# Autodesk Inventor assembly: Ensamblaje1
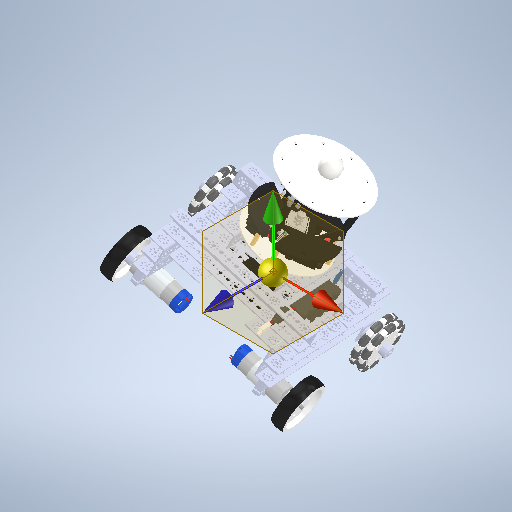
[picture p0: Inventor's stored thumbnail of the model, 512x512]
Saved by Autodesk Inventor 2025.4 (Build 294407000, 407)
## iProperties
Created: 2026-09
Part Number: Ensamblaje1
Document SubType Name: Assembly
Designer: usuario
Mass: 1778.88 g
Surface Area: 10785.4 cm^2
Volume: 1778.88 cm^3
Density: 1 g/cm^3
Author: usuario
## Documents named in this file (21)
- D:\Utec\Ciclo10\DSM\tetrix-solidworks-parts-1.snapshot.6\Nueva carpeta\DIseño\DIseño\Ensamblaje1.iam
- D:\Utec\Ciclo10\DSM\tetrix-solidworks-parts-1.snapshot.6\DIseño\Piezas\Tetrix 4 inch Dual Omni Wheel(2).ipt
- D:\Utec\Ciclo10\DSM\tetrix-solidworks-parts-1.snapshot.6\DIseño\Piezas\Tetrix 4 inch Wheel.ipt
- D:\Utec\Ciclo10\DSM\tetrix-solidworks-parts-1.snapshot.6\DIseño\Piezas\Tetrix 32mm Channel.ipt
- D:\Utec\Ciclo10\DSM\tetrix-solidworks-parts-1.snapshot.6\DIseño\Piezas\Tetrix 96mm Channel.ipt
- D:\Utec\Ciclo10\DSM\tetrix-solidworks-parts-1.snapshot.6\DIseño\Piezas\Tetrix Motor Mount.ipt
- D:\Utec\Ciclo10\DSM\tetrix-solidworks-parts-1.snapshot.6\DIseño\Piezas\Tetrix TorqueNADO DC Motor(2).ipt
- D:\Utec\Ciclo10\DSM\tetrix-solidworks-parts-1.snapshot.6\DIseño\Piezas\Tetrix Flat Building Plate.ipt
- D:\Utec\Ciclo10\DSM\tetrix-solidworks-parts-1.snapshot.6\DIseño\Piezas\Tetrix 416mm Channel.ipt
- D:\Utec\Ciclo10\DSM\tetrix-solidworks-parts-1.snapshot.6\DIseño\Piezas\Tetrix Gear Hub Spacer.ipt
- D:\Utec\Ciclo10\DSM\tetrix-solidworks-parts-1.snapshot.6\DIseño\Piezas\Tetrix Bronze Bushing 6mm.ipt
- D:\Utec\Ciclo10\DSM\tetrix-solidworks-parts-1.snapshot.6\DIseño\Piezas\Tetrix Flat 288mmx26mm.ipt
- D:\Utec\Ciclo10\DSM\tetrix-solidworks-parts-1.snapshot.6\DIseño\Piezas\Tetrix Battery Plate(2).ipt
- D:\Utec\Ciclo10\DSM\tetrix-solidworks-parts-1.snapshot.6\DIseño\Piezas\Motor Driver.ipt
- D:\Utec\Ciclo10\DSM\tetrix-solidworks-parts-1.snapshot.6\DIseño\Piezas\39057_txm-12v 3000mah battery pack assembly.ipt
- D:\Utec\Ciclo10\DSM\tetrix-solidworks-parts-1.snapshot.6\DIseño\ENSAMBLE_PLATO\ENSAMBLE_PLATO.iam
- D:\Utec\Ciclo10\DSM\tetrix-solidworks-parts-1.snapshot.6\DIseño\Piezas\myRIO-1900-MJG_v1.ipt
- D:\Utec\Ciclo10\DSM\tetrix-solidworks-parts-1.snapshot.6\DIseño\Piezas\Raspberry Pi 4 Model B.ipt
- D:\Utec\Ciclo10\DSM\tetrix-solidworks-parts-1.snapshot.6\DIseño\Piezas\Tetrix 160mm Channel.ipt
- D:\Utec\Ciclo10\DSM\tetrix-solidworks-parts-1.snapshot.6\DIseño\Piezas\Tetrix Flat 160mm x26mm.ipt
- D:\Utec\Ciclo10\DSM\tetrix-solidworks-parts-1.snapshot.6\DIseño\Piezas\Tetrix StandOff Post 6-32x28mm.ipt
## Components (51 placed, 20 different names)
1. Tetrix 4 inch Dual Omni Wheel(2):1 — Coincidencia:93, Coincidencia:96, Coincidencia:97, Coincidencia:98, Coincidencia:99
2. Tetrix 4 inch Dual Omni Wheel(2):2 — Coincidencia:73, Coincidencia:74, Coincidencia:75, Coincidencia:76
3. Tetrix 4 inch Wheel:1 — Coincidencia:31, Coincidencia:32, Coincidencia:33, Coincidencia:35
4. Tetrix 4 inch Wheel:2 — Coincidencia:1, Coincidencia:2, Coincidencia:6, Coincidencia:11
5. Tetrix 32mm Channel:2 — Coincidencia:12, Coincidencia:13, Coincidencia:93, Coincidencia:94, Coincidencia:95
6. Tetrix 32mm Channel:3 — Coincidencia:36, Coincidencia:37, Coincidencia:38, Coincidencia:39, Coincidencia:40, Coincidencia:41, Coincidencia:72
7. Tetrix 96mm Channel:3 — Coincidencia:46, Coincidencia:47, Coincidencia:48, Coincidencia:61, Coincidencia:64, Coincidencia:66
8. Tetrix Motor Mount:1 — Coincidencia:7, Coincidencia:8, Coincidencia:9, Coincidencia:10, Coincidencia:11
9. Tetrix Motor Mount:2 — Coincidencia:27, Coincidencia:28, Coincidencia:29, Coincidencia:30, Coincidencia:35
10. Tetrix TorqueNADO DC Motor(2):1 — Coincidencia:3, Coincidencia:4, Coincidencia:5, Coincidencia:10
11. Tetrix TorqueNADO DC Motor(2):2 — Coincidencia:30, Coincidencia:31, Coincidencia:34
12. Tetrix Flat Building Plate:1 — Coincidencia:89, Coincidencia:90, Coincidencia:91, Coincidencia:114, Coincidencia:142
13. Tetrix Flat Building Plate:2 — Coincidencia:86, Coincidencia:87, Coincidencia:88, Coincidencia:133, Coincidencia:135, Coincidencia:150
14. Tetrix 416mm Channel:1
15. Tetrix Gear Hub Spacer:1 — Coincidencia:5, Coincidencia:6
16. Tetrix Gear Hub Spacer:2 — Coincidencia:1, Coincidencia:2, Coincidencia:3, Coincidencia:4
17. Tetrix Gear Hub Spacer:3 — Coincidencia:94, Coincidencia:95, Coincidencia:96
18. Tetrix Gear Hub Spacer:4 — Coincidencia:32, Coincidencia:33, Coincidencia:34
19. Tetrix Gear Hub Spacer:5 — Coincidencia:97, Coincidencia:98, Coincidencia:99
20. Tetrix Bronze Bushing 6mm:2 — Coincidencia:40, Coincidencia:41
21. Tetrix Bronze Bushing 6mm:3 — Coincidencia:38, Coincidencia:39, Coincidencia:71
22. Tetrix 416mm Channel:2
23. Tetrix 416mm Channel:3
24. Tetrix 96mm Channel:4 — Coincidencia:49, Coincidencia:50, Coincidencia:51, Coincidencia:62, Coincidencia:65, Coincidencia:67, Coincidencia:105, Coincidencia:107
25. Tetrix 96mm Channel:5 — Coincidencia:52, Coincidencia:53, Coincidencia:54, Coincidencia:91, Coincidencia:110, Coincidencia:111
26. Tetrix 96mm Channel:6 — Coincidencia:55, Coincidencia:56, Coincidencia:57, Coincidencia:68, Coincidencia:69, Coincidencia:70, Coincidencia:88
27. Tetrix 416mm Channel:4 — Coincidencia:68, Coincidencia:69, Coincidencia:70
28. Tetrix Gear Hub Spacer:8 — Coincidencia:71, Coincidencia:72, Coincidencia:73, Coincidencia:74
29. Tetrix Gear Hub Spacer:9 — Coincidencia:75, Coincidencia:76
30. Tetrix Flat 288mmx26mm:1 — Coincidencia:83, Coincidencia:84, Coincidencia:85, Coincidencia:116, Coincidencia:117, Coincidencia:118, Coincidencia:119, Coincidencia:162
31. Tetrix Flat 288mmx26mm:2 — Coincidencia:80, Coincidencia:81, Coincidencia:82, Coincidencia:86, Coincidencia:89, Coincidencia:163, Coincidencia:170
32. Tetrix Flat 288mmx26mm:3 — Coincidencia:77, Coincidencia:78, Coincidencia:79, Coincidencia:87, Coincidencia:90, Coincidencia:113, Coincidencia:115
33. Tetrix Battery Plate(2):1 — Coincidencia:110, Coincidencia:111, Coincidencia:148, Coincidencia:151, Coincidencia:152
34. Tetrix Battery Plate(2):2 — Coincidencia:105, Coincidencia:106, Coincidencia:107, Coincidencia:149, Coincidencia:155, Coincidencia:159
35. Motor Driver:1 — Coincidencia:113, Coincidencia:114, Coincidencia:115
36. 39057_txm-12v 3000mah battery pack assembly:1 — Coincidencia:142, Coincidencia:148, Coincidencia:149
37. ENSAMBLE_PLATO:1 [sub-assembly] — Coincidencia:168, Coincidencia:169
38. myRIO-1900-MJG_v1:1 — Coincidencia:162, Coincidencia:163, Coincidencia:164
39. Raspberry Pi 4 Model B:1 — Coincidencia:170, Coincidencia:171
40. Tetrix 160mm Channel:1 — Coincidencia:136, Coincidencia:137, Coincidencia:138, Coincidencia:139, Coincidencia:156, Coincidencia:157, Coincidencia:165
41. Tetrix Flat 160mm x26mm:2 — Coincidencia:120, Coincidencia:121, Coincidencia:122, Coincidencia:166
42. Tetrix StandOff Post 6-32x28mm:1 — Coincidencia:116, Coincidencia:117, Coincidencia:122
43. Tetrix StandOff Post 6-32x28mm:2 — Coincidencia:128, Coincidencia:129, Coincidencia:133
44. Tetrix StandOff Post 6-32x28mm:3 — Coincidencia:118, Coincidencia:119, Coincidencia:120, Coincidencia:121, Coincidencia:164
45. Tetrix StandOff Post 6-32x28mm:4 — Coincidencia:128, Coincidencia:129, Coincidencia:139
46. Tetrix StandOff Post 6-32x28mm:5 — Coincidencia:126, Coincidencia:127, Coincidencia:136, Coincidencia:138
47. Tetrix StandOff Post 6-32x28mm:6 — Coincidencia:126, Coincidencia:127, Coincidencia:135, Coincidencia:150
48. Tetrix StandOff Post 6-32x28mm:7 — Coincidencia:151, Coincidencia:152
49. Tetrix 160mm Channel:5 — Coincidencia:156, Coincidencia:157, Coincidencia:158, Coincidencia:167, Coincidencia:169
50. Tetrix StandOff Post 6-32x28mm:9 — Coincidencia:155, Coincidencia:158, Coincidencia:159
51. Tetrix Flat 160mm x26mm:3 — Coincidencia:165, Coincidencia:166, Coincidencia:167, Coincidencia:168, Coincidencia:171
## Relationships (123: Mate 123)
- Coincidencia:1 [Mate]: Tetrix 4 inch Wheel:2 ↔ Tetrix Gear Hub Spacer:2
- Coincidencia:2 [Mate]: Tetrix 4 inch Wheel:2 ↔ Tetrix Gear Hub Spacer:2
- Coincidencia:3 [Mate]: Tetrix TorqueNADO DC Motor(2):1 ↔ Tetrix Gear Hub Spacer:2
- Coincidencia:4 [Mate]: Tetrix TorqueNADO DC Motor(2):1 ↔ Tetrix Gear Hub Spacer:2
- Coincidencia:5 [Mate]: Tetrix TorqueNADO DC Motor(2):1 ↔ Tetrix Gear Hub Spacer:1
- Coincidencia:6 [Mate]: Tetrix 4 inch Wheel:2 ↔ Tetrix Gear Hub Spacer:1
- Coincidencia:7 [Mate]: Tetrix Motor Mount:1
- Coincidencia:8 [Mate]: Tetrix Motor Mount:1
- Coincidencia:9 [Mate]: Tetrix Motor Mount:1
- Coincidencia:10 [Mate]: Tetrix Motor Mount:1 ↔ Tetrix TorqueNADO DC Motor(2):1
- Coincidencia:11 [Mate]: Tetrix 4 inch Wheel:2 ↔ Tetrix Motor Mount:1
- Coincidencia:12 [Mate]: Tetrix 32mm Channel:2
- Coincidencia:13 [Mate]: Tetrix 32mm Channel:2
- Coincidencia:27 [Mate]: Tetrix Motor Mount:2
- Coincidencia:28 [Mate]: Tetrix Motor Mount:2
- Coincidencia:29 [Mate]: Tetrix Motor Mount:2
- Coincidencia:30 [Mate]: Tetrix Motor Mount:2 ↔ Tetrix TorqueNADO DC Motor(2):2
- Coincidencia:31 [Mate]: Tetrix 4 inch Wheel:1 ↔ Tetrix TorqueNADO DC Motor(2):2
- Coincidencia:32 [Mate]: Tetrix 4 inch Wheel:1 ↔ Tetrix Gear Hub Spacer:4
- Coincidencia:33 [Mate]: Tetrix 4 inch Wheel:1 ↔ Tetrix Gear Hub Spacer:4
- Coincidencia:34 [Mate]: Tetrix TorqueNADO DC Motor(2):2 ↔ Tetrix Gear Hub Spacer:4
- Coincidencia:35 [Mate]: Tetrix 4 inch Wheel:1 ↔ Tetrix Motor Mount:2
- Coincidencia:36 [Mate]: Tetrix 32mm Channel:3
- Coincidencia:37 [Mate]: Tetrix 32mm Channel:3
- Coincidencia:38 [Mate]: Tetrix 32mm Channel:3 ↔ Tetrix Bronze Bushing 6mm:3
- Coincidencia:39 [Mate]: Tetrix 32mm Channel:3 ↔ Tetrix Bronze Bushing 6mm:3
- Coincidencia:40 [Mate]: Tetrix 32mm Channel:3 ↔ Tetrix Bronze Bushing 6mm:2
- Coincidencia:41 [Mate]: Tetrix 32mm Channel:3 ↔ Tetrix Bronze Bushing 6mm:2
- Coincidencia:46 [Mate]: Tetrix 96mm Channel:3
- Coincidencia:47 [Mate]: Tetrix 96mm Channel:3
- Coincidencia:48 [Mate]: Tetrix 96mm Channel:3
- Coincidencia:49 [Mate]: Tetrix 96mm Channel:4
- Coincidencia:50 [Mate]: Tetrix 96mm Channel:4
- Coincidencia:51 [Mate]: Tetrix 96mm Channel:4
- Coincidencia:52 [Mate]: Tetrix 96mm Channel:5
- Coincidencia:53 [Mate]: Tetrix 96mm Channel:5
- Coincidencia:54 [Mate]: Tetrix 96mm Channel:5
- Coincidencia:55 [Mate]: Tetrix 96mm Channel:6
- Coincidencia:56 [Mate]: Tetrix 96mm Channel:6
- Coincidencia:57 [Mate]: Tetrix 96mm Channel:6
- Coincidencia:61 [Mate]: Tetrix 96mm Channel:3
- Coincidencia:62 [Mate]: Tetrix 96mm Channel:4
- Coincidencia:64 [Mate]: Tetrix 96mm Channel:3
- Coincidencia:65 [Mate]: Tetrix 96mm Channel:4
- Coincidencia:66 [Mate]: Tetrix 96mm Channel:3
- Coincidencia:67 [Mate]: Tetrix 96mm Channel:4
- Coincidencia:68 [Mate]: Tetrix 96mm Channel:6 ↔ Tetrix 416mm Channel:4
- Coincidencia:69 [Mate]: Tetrix 96mm Channel:6 ↔ Tetrix 416mm Channel:4
- Coincidencia:70 [Mate]: Tetrix 96mm Channel:6 ↔ Tetrix 416mm Channel:4
- Coincidencia:71 [Mate]: Tetrix Bronze Bushing 6mm:3 ↔ Tetrix Gear Hub Spacer:8
- Coincidencia:72 [Mate]: Tetrix 32mm Channel:3 ↔ Tetrix Gear Hub Spacer:8
- Coincidencia:73 [Mate]: Tetrix 4 inch Dual Omni Wheel(2):2 ↔ Tetrix Gear Hub Spacer:8
- Coincidencia:74 [Mate]: Tetrix 4 inch Dual Omni Wheel(2):2 ↔ Tetrix Gear Hub Spacer:8
- Coincidencia:75 [Mate]: Tetrix 4 inch Dual Omni Wheel(2):2 ↔ Tetrix Gear Hub Spacer:9
- Coincidencia:76 [Mate]: Tetrix 4 inch Dual Omni Wheel(2):2 ↔ Tetrix Gear Hub Spacer:9
- Coincidencia:77 [Mate]: Tetrix Flat 288mmx26mm:3
- Coincidencia:78 [Mate]: Tetrix Flat 288mmx26mm:3
- Coincidencia:79 [Mate]: Tetrix Flat 288mmx26mm:3
- Coincidencia:80 [Mate]: Tetrix Flat 288mmx26mm:2
- Coincidencia:81 [Mate]: Tetrix Flat 288mmx26mm:2
- Coincidencia:82 [Mate]: Tetrix Flat 288mmx26mm:2
- Coincidencia:83 [Mate]: Tetrix Flat 288mmx26mm:1
- Coincidencia:84 [Mate]: Tetrix Flat 288mmx26mm:1
- Coincidencia:85 [Mate]: Tetrix Flat 288mmx26mm:1
- Coincidencia:86 [Mate]: Tetrix Flat Building Plate:2 ↔ Tetrix Flat 288mmx26mm:2
- Coincidencia:87 [Mate]: Tetrix Flat Building Plate:2 ↔ Tetrix Flat 288mmx26mm:3
- Coincidencia:88 [Mate]: Tetrix Flat Building Plate:2 ↔ Tetrix 96mm Channel:6
- Coincidencia:89 [Mate]: Tetrix Flat Building Plate:1 ↔ Tetrix Flat 288mmx26mm:2
- Coincidencia:90 [Mate]: Tetrix Flat Building Plate:1 ↔ Tetrix Flat 288mmx26mm:3
- Coincidencia:91 [Mate]: Tetrix Flat Building Plate:1 ↔ Tetrix 96mm Channel:5
- Coincidencia:93 [Mate]: Tetrix 4 inch Dual Omni Wheel(2):1 ↔ Tetrix 32mm Channel:2
- Coincidencia:94 [Mate]: Tetrix 32mm Channel:2 ↔ Tetrix Gear Hub Spacer:3
- Coincidencia:95 [Mate]: Tetrix 32mm Channel:2 ↔ Tetrix Gear Hub Spacer:3
- Coincidencia:96 [Mate]: Tetrix 4 inch Dual Omni Wheel(2):1 ↔ Tetrix Gear Hub Spacer:3
- Coincidencia:97 [Mate]: Tetrix 4 inch Dual Omni Wheel(2):1 ↔ Tetrix Gear Hub Spacer:5
- Coincidencia:98 [Mate]: Tetrix 4 inch Dual Omni Wheel(2):1 ↔ Tetrix Gear Hub Spacer:5
- Coincidencia:99 [Mate]: Tetrix 4 inch Dual Omni Wheel(2):1 ↔ Tetrix Gear Hub Spacer:5
- Coincidencia:105 [Mate]: Tetrix 96mm Channel:4 ↔ Tetrix Battery Plate(2):2
- Coincidencia:106 [Mate]: Tetrix Battery Plate(2):2
- Coincidencia:107 [Mate]: Tetrix 96mm Channel:4 ↔ Tetrix Battery Plate(2):2
- Coincidencia:110 [Mate]: Tetrix 96mm Channel:5 ↔ Tetrix Battery Plate(2):1
- Coincidencia:111 [Mate]: Tetrix 96mm Channel:5 ↔ Tetrix Battery Plate(2):1
- Coincidencia:113 [Mate]: Tetrix Flat 288mmx26mm:3 ↔ Motor Driver:1
- Coincidencia:114 [Mate]: Tetrix Flat Building Plate:1 ↔ Motor Driver:1
- Coincidencia:115 [Mate]: Tetrix Flat 288mmx26mm:3 ↔ Motor Driver:1
- Coincidencia:116 [Mate]: Tetrix Flat 288mmx26mm:1 ↔ Tetrix StandOff Post 6-32x28mm:1
- Coincidencia:117 [Mate]: Tetrix Flat 288mmx26mm:1 ↔ Tetrix StandOff Post 6-32x28mm:1
- Coincidencia:118 [Mate]: Tetrix Flat 288mmx26mm:1 ↔ Tetrix StandOff Post 6-32x28mm:3
- Coincidencia:119 [Mate]: Tetrix Flat 288mmx26mm:1 ↔ Tetrix StandOff Post 6-32x28mm:3
- Coincidencia:120 [Mate]: Tetrix Flat 160mm x26mm:2 ↔ Tetrix StandOff Post 6-32x28mm:3
- Coincidencia:121 [Mate]: Tetrix Flat 160mm x26mm:2 ↔ Tetrix StandOff Post 6-32x28mm:3
- Coincidencia:122 [Mate]: Tetrix Flat 160mm x26mm:2 ↔ Tetrix StandOff Post 6-32x28mm:1
- Coincidencia:126 [Mate]: Tetrix StandOff Post 6-32x28mm:5 ↔ Tetrix StandOff Post 6-32x28mm:6
- Coincidencia:127 [Mate]: Tetrix StandOff Post 6-32x28mm:5 ↔ Tetrix StandOff Post 6-32x28mm:6
- Coincidencia:128 [Mate]: Tetrix StandOff Post 6-32x28mm:2 ↔ Tetrix StandOff Post 6-32x28mm:4
- Coincidencia:129 [Mate]: Tetrix StandOff Post 6-32x28mm:2 ↔ Tetrix StandOff Post 6-32x28mm:4
- Coincidencia:133 [Mate]: Tetrix Flat Building Plate:2 ↔ Tetrix StandOff Post 6-32x28mm:2
- Coincidencia:135 [Mate]: Tetrix Flat Building Plate:2 ↔ Tetrix StandOff Post 6-32x28mm:6
- Coincidencia:136 [Mate]: Tetrix 160mm Channel:1 ↔ Tetrix StandOff Post 6-32x28mm:5
- Coincidencia:137 [Mate]: Tetrix 160mm Channel:1
- Coincidencia:138 [Mate]: Tetrix 160mm Channel:1 ↔ Tetrix StandOff Post 6-32x28mm:5
- Coincidencia:139 [Mate]: Tetrix 160mm Channel:1 ↔ Tetrix StandOff Post 6-32x28mm:4
- Coincidencia:142 [Mate]: Tetrix Flat Building Plate:1 ↔ 39057_txm-12v 3000mah battery pack assembly:1
- Coincidencia:148 [Mate]: Tetrix Battery Plate(2):1 ↔ 39057_txm-12v 3000mah battery pack assembly:1
- Coincidencia:149 [Mate]: Tetrix Battery Plate(2):2 ↔ 39057_txm-12v 3000mah battery pack assembly:1
- Coincidencia:150 [Mate]: Tetrix Flat Building Plate:2 ↔ Tetrix StandOff Post 6-32x28mm:6
- Coincidencia:151 [Mate]: Tetrix Battery Plate(2):1 ↔ Tetrix StandOff Post 6-32x28mm:7
- Coincidencia:152 [Mate]: Tetrix Battery Plate(2):1 ↔ Tetrix StandOff Post 6-32x28mm:7
- Coincidencia:155 [Mate]: Tetrix Battery Plate(2):2 ↔ Tetrix StandOff Post 6-32x28mm:9
- Coincidencia:156 [Mate]: Tetrix 160mm Channel:1 ↔ Tetrix 160mm Channel:5
- Coincidencia:157 [Mate]: Tetrix 160mm Channel:1 ↔ Tetrix 160mm Channel:5
- Coincidencia:158 [Mate]: Tetrix 160mm Channel:5 ↔ Tetrix StandOff Post 6-32x28mm:9
- Coincidencia:159 [Mate]: Tetrix Battery Plate(2):2 ↔ Tetrix StandOff Post 6-32x28mm:9
- Coincidencia:162 [Mate]: Tetrix Flat 288mmx26mm:1 ↔ myRIO-1900-MJG_v1:1
- Coincidencia:163 [Mate]: Tetrix Flat 288mmx26mm:2 ↔ myRIO-1900-MJG_v1:1
- Coincidencia:164 [Mate]: myRIO-1900-MJG_v1:1 ↔ Tetrix StandOff Post 6-32x28mm:3
- Coincidencia:165 [Mate]: Tetrix 160mm Channel:1 ↔ Tetrix Flat 160mm x26mm:3
- Coincidencia:166 [Mate]: Tetrix Flat 160mm x26mm:2 ↔ Tetrix Flat 160mm x26mm:3
- Coincidencia:167 [Mate]: Tetrix 160mm Channel:5 ↔ Tetrix Flat 160mm x26mm:3
- Coincidencia:168 [Mate]: ENSAMBLE_PLATO:1 ↔ Tetrix Flat 160mm x26mm:3
- Coincidencia:169 [Mate]: ENSAMBLE_PLATO:1 ↔ Tetrix 160mm Channel:5
- Coincidencia:170 [Mate]: Tetrix Flat 288mmx26mm:2 ↔ Raspberry Pi 4 Model B:1
- Coincidencia:171 [Mate]: Raspberry Pi 4 Model B:1 ↔ Tetrix Flat 160mm x26mm:3
